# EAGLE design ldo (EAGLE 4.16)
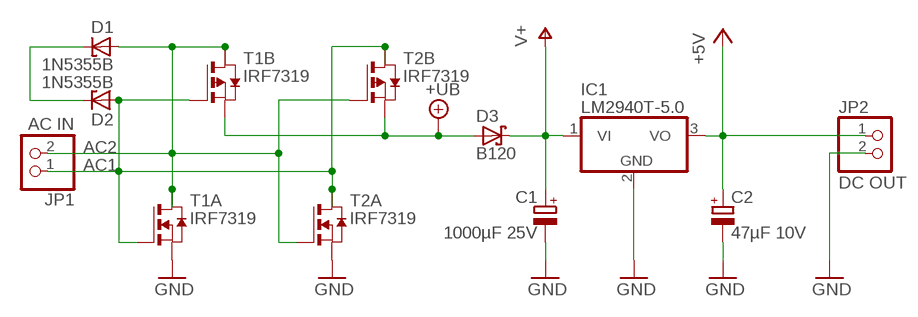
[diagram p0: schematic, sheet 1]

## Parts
C1  1000µF 25V  CPOL-EUTT5D11L  [TT5D11L]
C2  47µF 10V  CPOL-EUCT6032  [CT6032]
D1  1N5355B  1N5333  [C1702-15]
D2  1N5355B  1N5333  [C1702-15]
D3  B120  SCHOTTKY-DIODESMD  [SMB]
IC1  LM2940T-5.0  7805T  [TO220H]
JP1  AC IN  PINHD-1X2  [1X02]
JP2  DC OUT  PINHD-1X2  [1X02]
T1  IRF7319  PN_MOSFET-SO8  [SO8]
T2  IRF7319  PN_MOSFET-SO8  [SO8]

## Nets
+5V: C2.+ IC1.3(VO) JP2.1
+UB: D3.A T1.3(B:S) T2.3(B:S)
AC: D1.C D2.C
AC1: D2.A JP1.1 T1.2(A:G) T1.4(B:G) T2.5(B:D) T2.6(B:D2) T2.7(A:D) T2.8(A:D2)
AC2: D1.A JP1.2 T1.5(B:D) T1.6(B:D2) T1.7(A:D) T1.8(A:D2) T2.2(A:G) T2.4(B:G)
GND: C1.- C2.- IC1.2(GND) JP2.2 T1.1(A:S) T2.1(A:S)
V+: C1.+ D3.C IC1.1(VI)

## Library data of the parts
C1 C2 = rcl:CPOL-EU: POLARIZED CAPACITOR, European symbol
D1 D2 = diode:1N5333: Z DIODE
D3 = diode:SCHOTTKY-DIODE: Schottky Diode
IC1 = linear:78*: Positive VOLTAGE REGULATOR Source: http://cache.national.com/ds/LM/LM78L05.pdf http://www.fairchildsemi.com/ds/LM/LM7805.pdf
JP1 JP2 = pinhead:PINHD-1X2: PIN HEADER
T1 T2 = zetex:PN_MOSFET-: DUAL N AND P-CHANNEL ENHANCEMENT MODE MOSFET source ZXMD63C02.pdf from http://www.zetex.com/

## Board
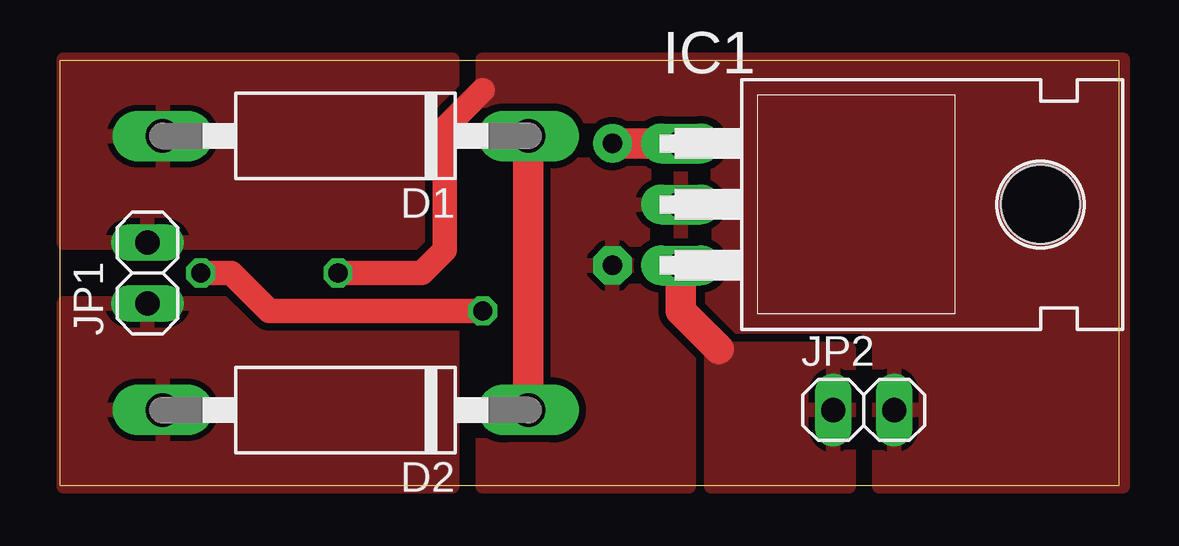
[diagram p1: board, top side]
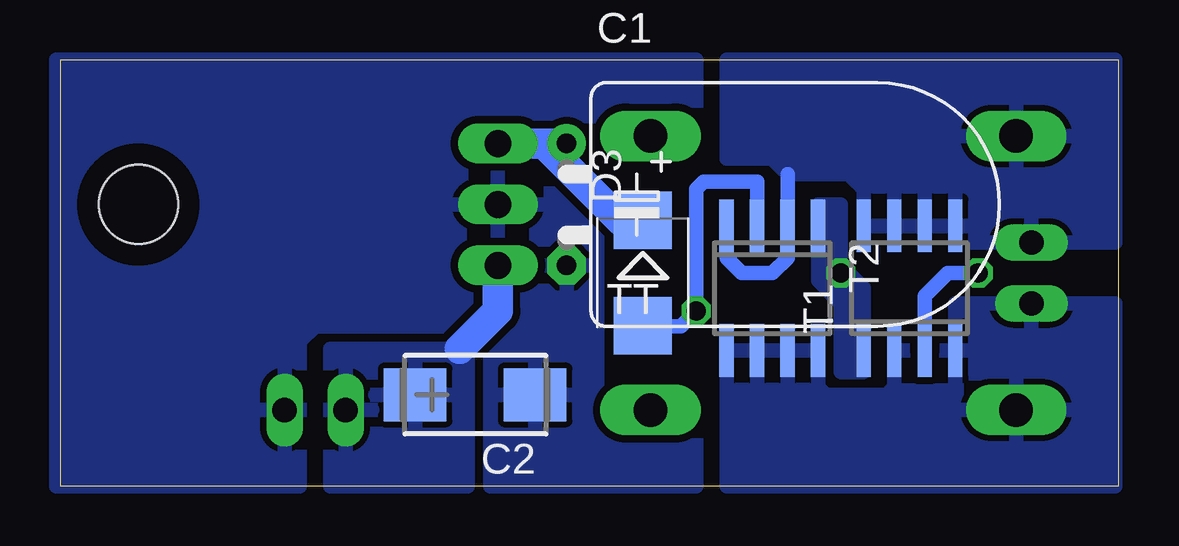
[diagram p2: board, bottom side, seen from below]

Size 44.12 x 17.77 mm. Coordinates in mm from the lower left corner, seen from the top.
Outline: 0,17.77 44.12,17.77 44.12,0 0,0 0,17.77
Copper layers (1*16): Top 0.035mm / dielectric 1.5mm / Bottom 0.035mm
Design rules "default": minimum track width 8mil, minimum drill 24mil, track to track 12mil, track to pad 12mil, pad to pad 12mil, via to via 12mil, smd to smd 8mil, copper to edge 0mil, drill to drill 12mil, minimum pad ring 10mil, minimum via ring 8mil, stop-mask expansion 4mil, vias tented up to drill 0mil, thermal gap 10mil

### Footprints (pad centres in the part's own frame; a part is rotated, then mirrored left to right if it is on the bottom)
TT5D11L = drill 0.813 pad 1.6 round: + -2.54,0 | drill 0.813 pad 1.6 octagon: - 2.54,0
CT6032 = smd 2.6 x 2.2: + 2.5,0; - -2.5,0
C1702-15 = drill 1.397 long: A 7.62,0; C -7.62,0
SMB = smd 2.4 x 2.4: A 2.2,0; C -2.2,0
TO220H = drill 1.118 long: 1 -2.54,-10.16; 2 0,-10.16; 3 2.54,-10.16 | hole 3.302: 0,4.826
1X02 = drill 1.016 long: 1 -1.27,0; 2 1.27,0
SO8 = smd 0.6 x 2.2: 1 -1.905,-2.6; 2 -0.635,-2.6; 3 0.635,-2.6; 4 1.905,-2.6; 5 1.905,2.6; 6 0.635,2.6; 7 -0.635,2.6; 8 -1.905,2.6

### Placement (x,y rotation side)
C1  23.01,11.74 270 bottom
C2  26.82,3.8 180 bottom
D1  11.9,14.6 180 top
D2  11.9,3.17 180 top
D3  19.84,8.89 270 bottom
IC1  36.03,11.74 270 top
JP1  3.65,8.89 90 top
JP2  33.49,3.17 0 top
T1  8.73,8.25 0 bottom
T2  14.44,8.25 180 bottom

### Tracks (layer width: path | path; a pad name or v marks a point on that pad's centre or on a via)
+5V
  Top 1.27: IC1.3 25.87,7.3 27.46,5.71
  Bottom 1.27: IC1.3 25.87,7.3 27.46,5.71
  pour Bottom: 27.14,5.71 32.86,5.71 32.86,-0.01 27.14,-0.01
  pour Top: 32.86,5.71 32.86,-0.01 27.14,-0.01 27.14,5.71
+UB  (via drill 0.8)
  Top 1.016: v17.62,7.3 8.73,7.3 7.14,8.89 v5.87,8.89
  Bottom 0.61: 15.08,10.79 T2.3 15.08,12.7 17.3,12.7 17.62,12.38 v17.62,7.3 18.25,6.66 19.84,6.66 D3.A | T1.3 8.09,7.93 7.14,8.89 v5.87,8.89
AC
  Top 1.27: D2.C D1.C
AC1
  Top 1.27: D2.A 3.65,3.17
  Bottom 0.61: T2.8 12.54,6.34
  pour Bottom: 0.15,7.62 6.82,7.62 6.82,6.34 9.36,6.34 9.36,4.12 9.68,3.8 12.22,3.8 12.54,4.12 12.54,6.34 16.35,6.34 16.35,-0.01 0.15,-0.01
  pour Top: 0.15,7.62 16.35,7.62 16.35,-0.01 0.15,-0.01
AC2
  Bottom 0.61: T2.4 16.35,9.52 15.71,8.89 14.44,8.89 13.81,9.52 T2.2 13.81,13.01
  pour Bottom: 0.15,17.77 16.35,17.77 16.35,13.65 14.44,13.65 13.81,13.01 11.27,13.01 10.63,12.38 10.63,10.16 0.15,10.16
  pour Top: 0.15,10.16 16.35,10.16 16.35,17.77 0.15,17.77
GND  (via drill 0.8)
  Top 1.016: v11.58,8.89 15.08,8.89 16.03,9.84 16.03,14.92 17.62,16.5
  pour Bottom: 44.29,17.77 17.62,17.77 17.62,13.65 21.74,13.65 21.74,4.12 17.62,4.12 17.62,-0.01 26.19,-0.01 26.19,6.34 26.51,6.66 33.49,6.66 34.12,6.03 34.12,-0.01 44.29,-0.01
  pour Top: 17.62,17.77 44.29,17.77 44.29,-0.01 34.12,-0.01 34.12,6.03 33.49,6.66 26.51,6.66 26.19,6.34 26.19,-0.01 17.62,-0.01
  pour Bottom (no thermals): 11.58,11.74 12.54,11.74 12.54,8.57 11.58,7.62 11.58,4.76 10.63,4.76 10.63,8.25 11.58,9.2
V+
  Top 1.27: IC1.1 C1.+
  Bottom 1.27: D3.C 20.77,11.09 23.96,14.28 | 23.96,14.28 IC1.1 | 23.96,14.28 C1.+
